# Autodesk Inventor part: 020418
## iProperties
Shininess: 60.0
Length Units: 11269
Angle Units: 11279
Time Units: 11290
Mass Units: 11283
Length Display Precision: 3
Angle Display Precision: 2
Compacted: True
Company: Pneumax S.p.A.
Part Number: 020418
Description: RACCORDO DIRITTO FEMMINA G1/8 Ø4
Document SubType Name: Modellazione
Catalog Web Link: www.pneumaxspa.com
Density: 0.0
Volumn: 0.0
Area: 0.0
PropertySet Name: Model Information
Control State: 0
Master: False
Checked Out: False
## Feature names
1. Rivoluzione1 [Revolution]
2. Revolution3
3. Estrusione1 [Extrusion]
4. Serie circolare1 [Circular Pattern]
5. Foro1 [Hole]
6. Chamfer5
